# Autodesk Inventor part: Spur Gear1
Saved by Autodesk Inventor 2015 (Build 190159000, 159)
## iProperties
Created: 2014-08
Part Number: Spur Gear1
Material: Steel
Document SubType Name: Modeling
Designer: User
Categories: <?xml version="1.0" encoding="UTF-16"?> <MemberInstance><Categories><FamilyTemplate><FamilyTemplateParameter ValueType="xs:double" Id="1" ObjectReferenceKey="da
Density: 1 g/cm^3
Appearance: Steel
CustomPartVersion: 1
Author: User
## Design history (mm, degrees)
sketch "Sketch1"
  geometry: C1 r 6.544 at (0, 0)
  constraints: 1 centre point
  dimensions: "d0" = 13.08758 diameter of C1 (= da_da)
extrude "Extrusion1" new body sketch "Sketch1" distance "d1" = 4 (= da_b); taper "d2" = 0 deg
workplane "Work Plane2"
sketch "Sketch2"
  geometry: C1 r 6.544 at (0, 0) reference; C2 r 5.75 at (0, 0)
  constraints: 1 centre point, 1 coincident
  dimensions: "d3" = 11.5 diameter of C2 (= da_dw)
feature "Pitch Diameter" sketch "Sketch2" dims "d4" = 10, "d5" = 0
workplane "Work Plane8"
workplane "Work Plane9"
feature "Spur Gear" dims "da_b" = 4, "da_d" = 11.48758, "da_aw" = 11.5, "da_da" = 13.08758, "da_df" = 9.48758, "da_dw" = 11.5, angle "da_beta" = 40 deg, "da_lefttooth" = 10, "da_righttooth" = 0
body "Solid1"
body "Srf1"
other parameters: "d16" = 11.5 (= da_aw), "d17" = 0, "d34" = 2.85599 (computed from da_z), "d39" = 0, "d41" = 0, "d43" = 11.5 (= da_aw), "d46" = 11.5 (= da_aw), "d47" = 0, "d48" = 0
